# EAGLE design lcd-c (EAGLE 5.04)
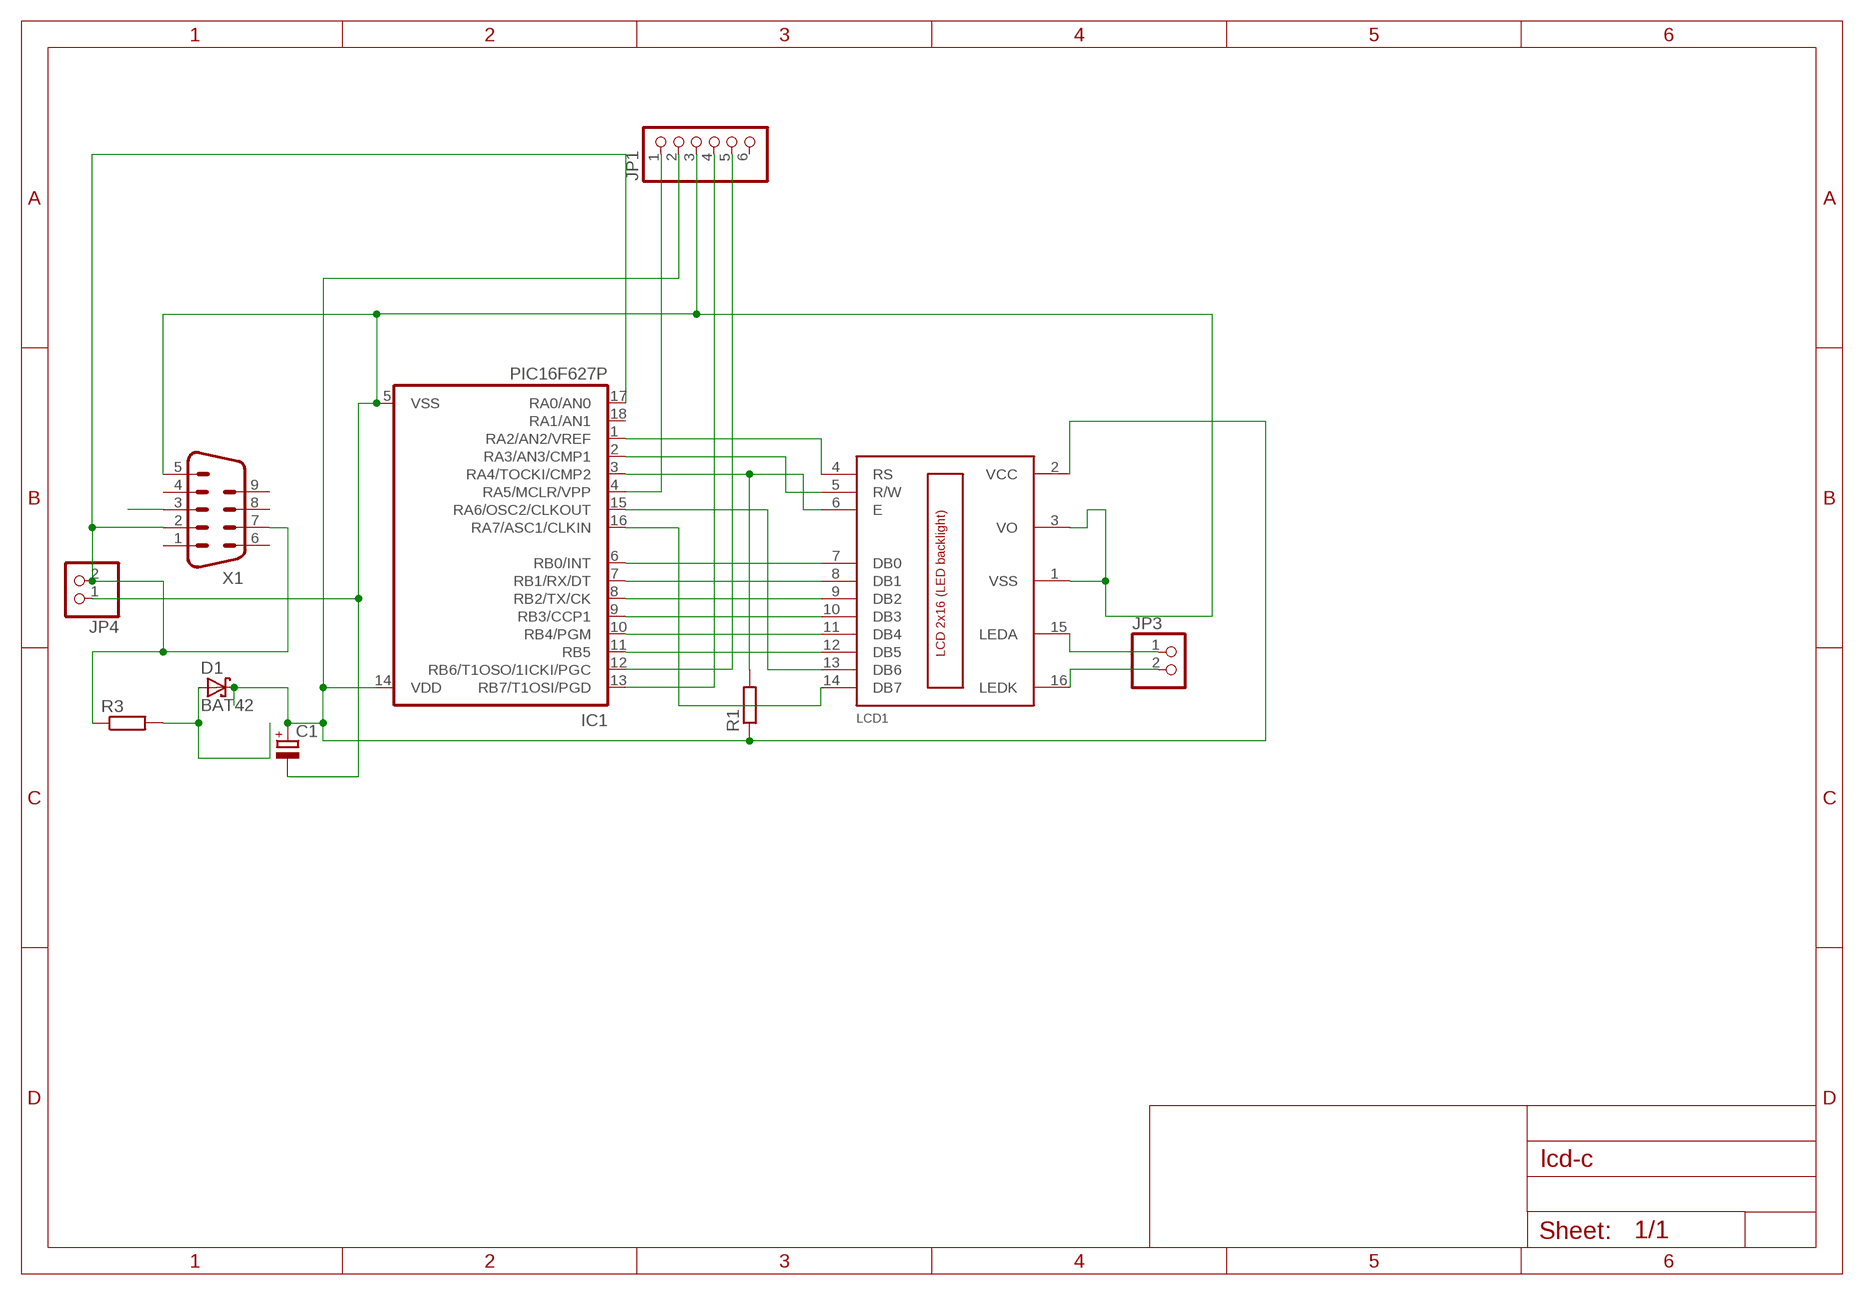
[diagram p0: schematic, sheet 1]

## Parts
C1  CPOL-EUE2.5-6  [E2,5-6]
D1  BAT42  [DO35-10]
IC1  PIC16F627P  [DIL18]
JP1  PINHD-1X6  [1X06]
JP3  PINHD-1X2  [1X02]
JP4  PINHD-1X2  [1X02]
LCD1  LCD_2X16  [HY-1602F]
R1  R-EU_0204/2V  [0204V]
R3  R-EU_0204/2V  [0204V]
X1  M09HP  [M09HP]

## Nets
N$1: IC1.4(RA5/MCLR/VPP) JP1.1
N$2: IC1.12(RB6/T1OSO/1ICKI/PGC) JP1.5
N$3: IC1.13(RB7/T1OSI/PGD) JP1.4
N$4: IC1.15(RA6/OSC2/CLKOUT) LCD1.13(DB6)
N$5: IC1.16(RA7/ASC1/CLKIN) LCD1.14(DB7)
N$6: IC1.11(RB5) LCD1.12(DB5)
N$7: IC1.10(RB4/PGM) LCD1.11(DB4)
N$8: IC1.9(RB3/CCP1) LCD1.10(DB3)
N$9: IC1.8(RB2/TX/CK) LCD1.9(DB2)
N$10: IC1.7(RB1/RX/DT) LCD1.8(DB1)
N$11: IC1.6(RB0/INT) LCD1.7(DB0)
N$12: IC1.3(RA4/TOCKI/CMP2) LCD1.6(E) R1.2
N$13: IC1.1(RA2/AN2/VREF) LCD1.4(RS)
N$14: IC1.2(RA3/AN3/CMP1) LCD1.5(R/W)
N$15: JP3.2 LCD1.16(LEDK)
N$16: JP3.1 LCD1.15(LEDA)
N$17: D1.A R3.2
N$19: X1.3
N$20: IC1.17(RA0/AN0) JP4.2 R3.1 X1.2 X1.7
VDD: C1.+ D1.C IC1.14(VDD) JP1.2 LCD1.2(VCC) R1.1
VSS: C1.- IC1.5(VSS) JP1.3 JP4.1 LCD1.1(VSS) LCD1.3(VO) X1.5
Unconnected: IC1.18(RA1/AN1) JP1.6 X1.1 X1.4 X1.6 X1.8 X1.9

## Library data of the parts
C1 = rcl-2:CPOL-EU: POLARIZED CAPACITOR, European symbol
D1 = diode-1:BAT42: DIODE
IC1 = microchip:PIC16*F62: FLASH-Based 8-Bit CMOS Microcontroller Source: http://ww1.microchip.com/downloads/en/DeviceDoc/40300C.pdf
JP1 = pinhead:PINHD-1X6: PIN HEADER
JP3 = pinhead:PINHD-1X2: PIN HEADER
JP4 = pinhead(2):PINHD-1X2: PIN HEADER
LCD1 = lcd_2x16_led_backlight:LCD_2X16
R1 R3 = rcl-2:R-EU_: RESISTOR, European symbol
X1 = con-subd:M09: SUB-D

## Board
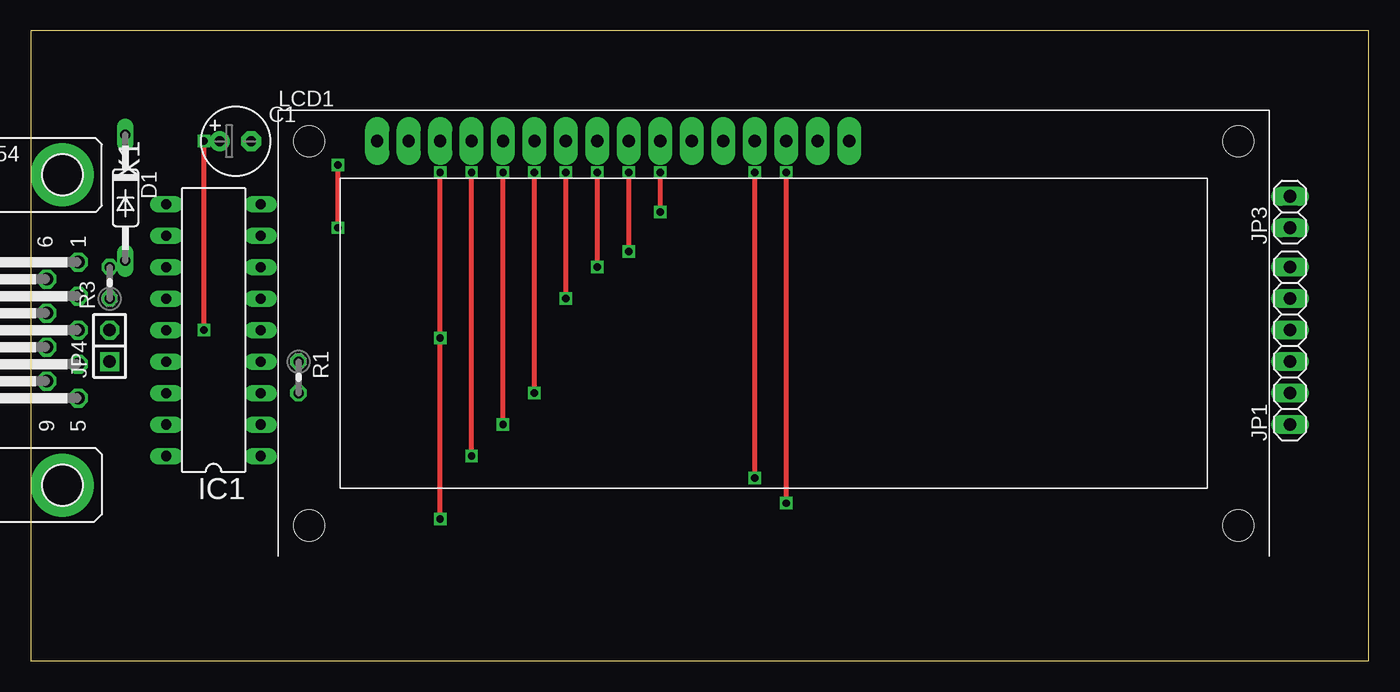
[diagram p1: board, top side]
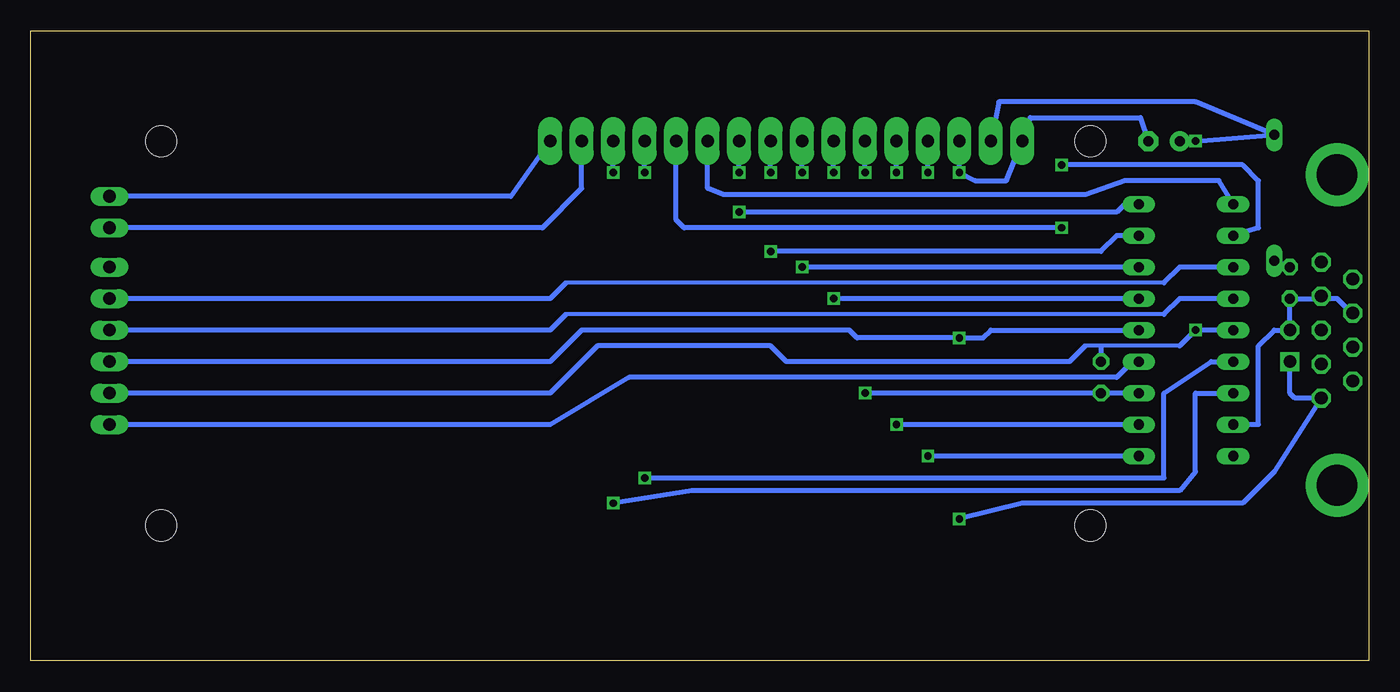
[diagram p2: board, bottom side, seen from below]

Size 107.95 x 50.8 mm. Coordinates in mm from the lower left corner, seen from the top.
Outline: 0,0 107.95,0 107.95,50.8 0,50.8 0,0
Copper layers (1*16): Top 0.035mm / dielectric 1.5mm / Bottom 0.035mm
Design rules "default": minimum track width 10mil, minimum drill 24mil, track to track 8mil, track to pad 8mil, pad to pad 8mil, via to via 8mil, smd to smd 8mil, copper to edge 40mil, drill to drill 8mil, minimum pad ring 10mil, minimum via ring 8mil, stop-mask expansion 4mil, vias tented up to drill 0mil, thermal gap 10mil

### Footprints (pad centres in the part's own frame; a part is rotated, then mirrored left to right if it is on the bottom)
E2,5-6 = drill 0.813 pad 1.6 round: + -1.27,0 | drill 0.813 pad 1.6 octagon: - 1.27,0
DO35-10 = drill 0.813 long: A 5.08,0; C -5.08,0
DIL18 = drill 0.813 long: 1 -10.16,-3.81; 2 -7.62,-3.81; 3 -5.08,-3.81; 4 -2.54,-3.81; 5 0,-3.81; 6 2.54,-3.81; 7 5.08,-3.81; 8 7.62,-3.81; 9 10.16,-3.81; 10 10.16,3.81; 11 7.62,3.81; 12 5.08,3.81; 13 2.54,3.81; 14 0,3.81; 15 -2.54,3.81; 16 -5.08,3.81; 17 -7.62,3.81; 18 -10.16,3.81
1X06 = drill 1.016 long: 1 -6.35,0; 2 -3.81,0; 3 -1.27,0; 4 1.27,0; 5 3.81,0; 6 6.35,0
1X02 = drill 1.016 long: 1 -1.27,0; 2 1.27,0
1X02' = drill 1.016 square: 1 -1.27,0 | drill 1.016 octagon: 2 1.27,0
HY-1602F = drill 1 pad 1.93 long: 1 2.54,0; 2 5.08,0; 3 7.62,0; 4 10.16,0; 5 12.7,0; 6 15.24,0; 7 17.78,0; 8 20.32,0; 9 22.86,0; 10 25.4,0; 11 27.94,0; 12 30.48,0; 13 33.02,0; 14 35.56,0; 15 38.1,0; 16 40.64,0 | hole 2.5: -2.96,0; 72.04,0; -2.96,-31; 72.04,-31
0204V = drill 0.813 octagon: 1 -1.27,0; 2 1.27,0
M09HP = drill 1.016 octagon: 1 -5.486,1.27; 2 -2.743,1.27; 3 0,1.27; 4 2.743,1.27; 5 5.486,1.27; 6 -4.115,-1.27; 7 -1.372,-1.27; 8 1.372,-1.27; 9 4.115,-1.27 | drill 3.302 pad 5.08 round: G1 -12.522,0; G2 12.522,0

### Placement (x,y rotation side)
C1  16.51,41.91 0 top
D1  7.62,37.34 270 top
IC1  14.73,26.67 90 top
JP1  101.6,25.4 90 top
JP3  101.6,36.2 90 top
JP4  [1X02']  6.35,25.4 90 top
LCD1  25.4,41.91 0 top
R1  21.59,22.86 270 top
R3  6.35,30.48 90 top
X1  2.54,26.67 270 top

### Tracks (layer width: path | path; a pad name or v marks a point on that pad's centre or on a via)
N$1
  Bottom 0.406: JP1.1 66.04,19.05 59.69,22.86 20.32,22.86 19.05,24.13 IC1.4
N$2
  Bottom 0.305: 16.51,30.48 64.77,30.48
  Bottom 0.406: JP1.5 66.04,29.21 64.77,30.48 | 16.51,30.48 15.24,31.75 IC1.12
N$3
  Bottom 0.305: 16.51,27.94 64.77,27.94
  Bottom 0.406: JP1.4 66.04,26.67 64.77,27.94 | 16.51,27.94 15.24,29.21 IC1.13
N$4  (via drill 0.6)
  Top 0.406: v58.42,14.73 v58.42,39.37
  Bottom 0.406: v58.42,14.73 16.51,14.73 16.51,21.59 12.7,24.13 IC1.15 | v58.42,39.37 LCD1.13 v58.42,39.37
N$5  (via drill 0.6)
  Top 0.406: v60.96,12.7 v60.96,39.37
  Bottom 0.406: IC1.16 13.97,21.59 13.97,15.24 15.24,13.72 54.61,13.72 v60.96,12.7 | v60.96,39.37 LCD1.14
N$6  (via drill 0.6)
  Top 0.406: v24.77,40.01 v24.77,34.92
  Bottom 0.406: LCD1.12 55.88,35.56 55.24,34.92 v24.77,34.92 | IC1.11 8.89,34.92 8.89,38.73 10.16,40.01 v24.77,40.01
N$7
  Bottom 0.406: IC1.10 12.06,38.73 19.68,38.73 22.86,37.59 52.07,37.59 53.34,38.1 LCD1.11
N$8  (via drill 0.6)
  Top 0.406: v50.8,36.2 v50.8,39.37
  Bottom 0.406: IC1.9 19.68,36.83 20.32,36.2 v50.8,36.2 | v50.8,39.37 LCD1.10
N$9  (via drill 0.6)
  Top 0.406: v48.26,33.02 v48.26,39.37
  Bottom 0.406: v48.26,39.37 LCD1.9 | IC1.8 20.32,34.29 21.59,33.02 v48.26,33.02
N$10  (via drill 0.6)
  Top 0.406: v45.72,31.75 v45.72,39.37
  Bottom 0.406: v45.72,39.37 LCD1.8 | IC1.7 v45.72,31.75
N$11  (via drill 0.6)
  Top 0.406: v43.18,29.21 v43.18,39.37
  Bottom 0.406: v43.18,39.37 LCD1.7 | IC1.6 v43.18,29.21
N$12  (via drill 0.6)
  Top 0.406: v40.64,21.59 v40.64,39.37
  Bottom 0.406: v40.64,39.37 LCD1.6 | IC1.3 19.05,21.59 R1.2 v40.64,21.59
N$13  (via drill 0.6)
  Top 0.406: v35.56,16.51 v35.56,39.37
  Bottom 0.406: v35.56,39.37 LCD1.4 | IC1.1 v35.56,16.51
N$14  (via drill 0.6)
  Top 0.406: v38.1,19.05 v38.1,39.37
  Bottom 0.406: v38.1,39.37 LCD1.5 | IC1.2 v38.1,19.05
N$15
  Bottom 0.406: JP3.2 69.22,37.47 LCD1.16
N$16
  Bottom 0.406: LCD1.15 63.5,38.1 66.67,34.92 JP3.1
N$17
  Bottom 0.406: R3.2 D1.A
N$20
  Bottom 0.406: IC1.17 8.89,19.05 8.89,25.4 7.62,26.67 JP4.2 R3.1 4.01,29.21 X1.2 3.61,29.21 2.54,29.21 1.37,28.04 X1.7
VDD  (via drill 0.6)
  Top 0.406: v13.97,26.67 v13.97,41.91
  Bottom 0.305: 15.24,25.4 21.59,25.4 22.86,25.4
  Bottom 0.406: LCD1.2 29.84,45.09 13.97,45.09 D1.C v13.97,41.91 C1.+ | JP1.2 66.04,21.59 62.23,25.4 48.26,25.4 46.99,24.13 24.13,24.13 22.86,25.4 | 15.24,25.4 v13.97,26.67 IC1.14 | 21.59,25.4 R1.1
VSS  (via drill 0.6)
  Top 0.406: v33.02,39.37 v33.02,26.04 v33.02,11.43
  Bottom 0.406: LCD1.3 v33.02,39.37 31.75,38.73 29.21,38.73 LCD1.1 27.3,43.81 18.41,43.81 C1.- | IC1.5 30.48,26.67 31.11,26.04 v33.02,26.04 41.27,26.04 41.91,26.67 63.5,26.67 66.04,24.13 JP1.3 | v33.02,11.43 27.94,12.7 10.16,12.7 7.62,15.24 X1.5 5.94,21.18 6.35,21.59 JP4.1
